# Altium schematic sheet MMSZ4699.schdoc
size 127 x 101 mm
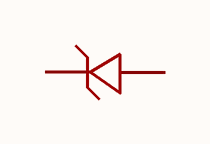
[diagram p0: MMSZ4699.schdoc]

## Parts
ZD?  mmsz4699  [SOD-123_L2.8-W1.8-LS3.7-RD]  (value not drawn)

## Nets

Not connected (* = marked no-connect by the designer): ZD? 1(K) 2(A)

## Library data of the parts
ZD? = mmsz4699: 二极管配置:1个独立式;稳压值(标称值):12V;稳压值(范围):11.4V~12.6V;耗散功率(Pd):350mW;; Manufacturer: CJ(江苏长电/长晶); AddInBom: yes; ModelId: 7884390a25fb4c08947731ebfba7e3f8; ModelTransform: 144.8816,62.992,0,0,0,0,0,0,0; Diode Configuration: 1个独立式; Zener Voltage(Nom): 12V; Reverse Leakage Current (Ir): 50nA@9.1V; Pd - Power Dissipation: 350mW; Operating Junction Temperature Range: -65℃~+150℃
